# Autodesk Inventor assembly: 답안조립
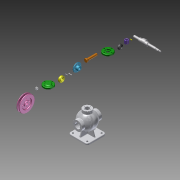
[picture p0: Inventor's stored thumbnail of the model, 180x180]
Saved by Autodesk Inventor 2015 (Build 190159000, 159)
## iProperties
Created: 2025-08
Part Number: 답안조립
Document SubType Name: Assembly
Designer: USER
Author: USER
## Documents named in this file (15)
- C:\Users\USER\Downloads\750808V1009\답안조립.iam
- C:\Users\USER\Downloads\750808V1009\본체.ipt
- C:\Users\USER\Downloads\750808V1009\가져온 구성요소\V-벨트풀리\V-벨트풀리.ipt
- C:\Users\USER\Downloads\750808V1009\가져온 구성요소\너트 M8\너트 M8.ipt
- C:\Users\USER\Downloads\750808V1009\가져온 구성요소\뒤커버\뒤커버.ipt
- C:\Users\USER\Downloads\750808V1009\가져온 구성요소\베어링- 6202\베어링- 6202.ipt
- C:\Users\USER\Downloads\750808V1009\가져온 구성요소\볼트 M4 x 12\볼트 M4 x 12.ipt
- C:\Users\USER\Downloads\750808V1009\가져온 구성요소\볼트 M4 x 16\볼트 M4 x 16.ipt
- C:\Users\USER\Downloads\750808V1009\가져온 구성요소\상부커버\상부커버.ipt
- C:\Users\USER\Downloads\750808V1009\가져온 구성요소\슬라이드\슬라이드.ipt
- C:\Users\USER\Downloads\750808V1009\가져온 구성요소\앞커버\앞커버.ipt
- C:\Users\USER\Downloads\750808V1009\가져온 구성요소\오일실 15 30 7\오일실 15 30 7.ipt
- C:\Users\USER\Downloads\750808V1009\가져온 구성요소\칼라\칼라.ipt
- C:\Users\USER\Downloads\750808V1009\가져온 구성요소\키 4 x 4 x 12\키 4 x 4 x 12.ipt
- C:\Users\USER\Downloads\750808V1009\가져온 구성요소\편심축\편심축.ipt
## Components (1 placed, 1 different names)
1. V-벨트풀리:1
